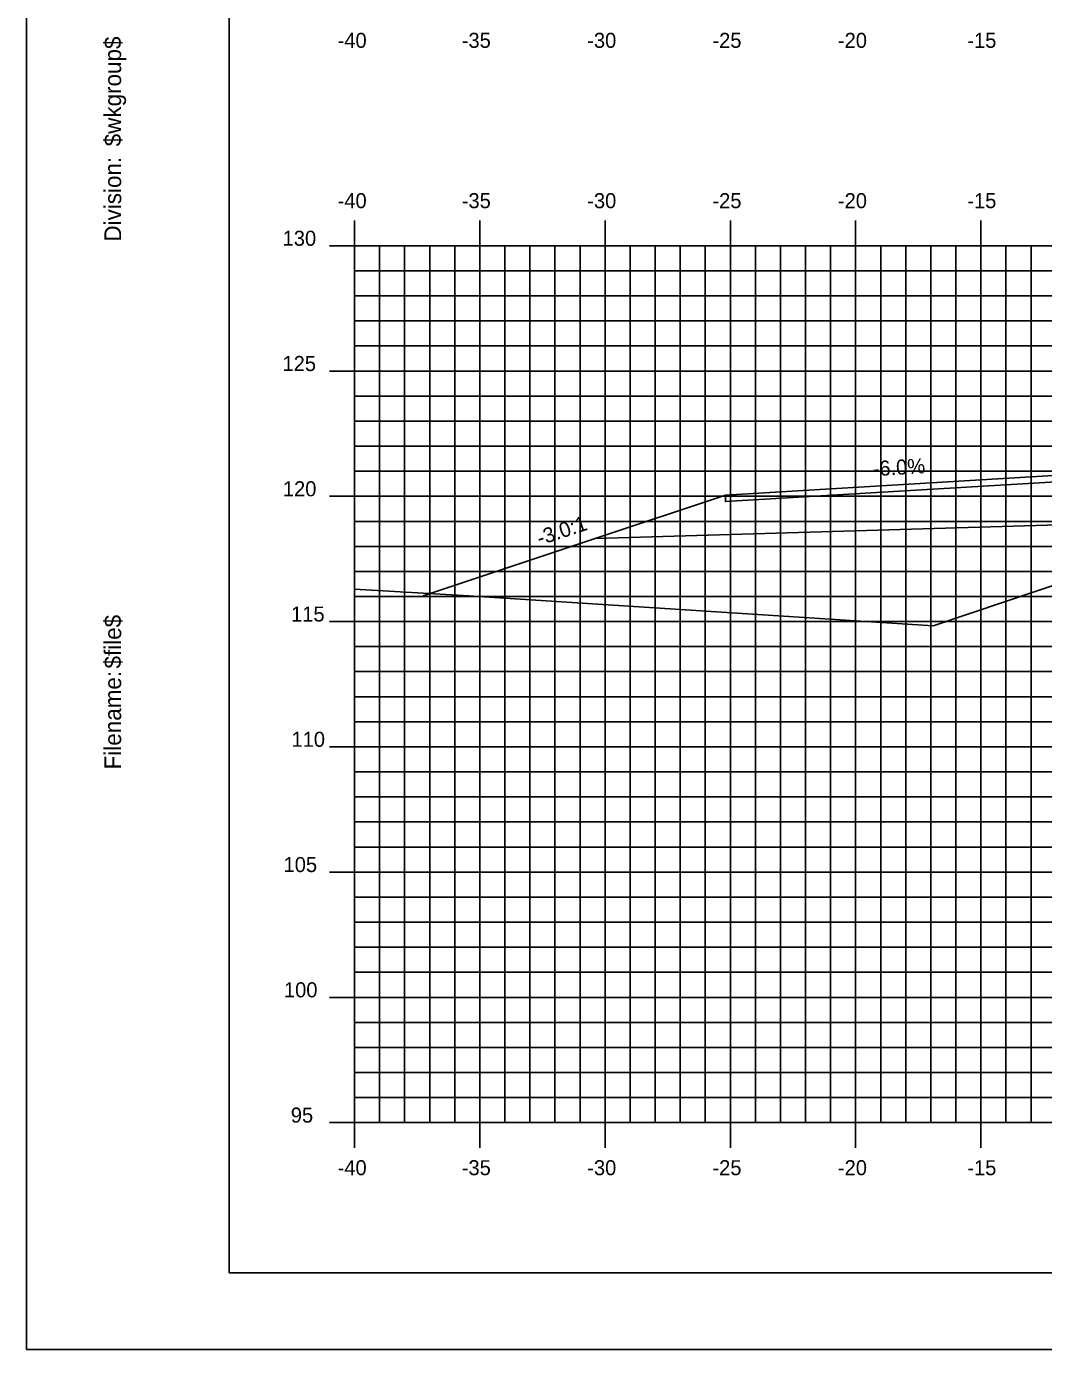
# Model space of a CAD drawing. Extents: x 850598 to 870284, y 366541 to 366651.
# Drawn here: x 859024.6 to 859065.1, y 366541.2 to 366594 of the extents above; entities that cross this region are included whole.
import ezdxf

# ---------------------------------------------------------------- set-up
doc = ezdxf.new("R2010")
doc.units = 0
for name, color, linetype in [('ANNOTATION', 7, 'Continuous'), ('BORDER', 7, 'Continuous'), ('D_Roadway_Centerline', 7, 'Continuous'), ('D_Roadway_Edge_Shoulder', 7, 'Continuous'), ('D_Roadway_SlopeLines', 7, 'Continuous'), ('D_Roadway_SubGrade', 7, 'Continuous'), ('H_V ANNOTATION', 7, 'Continuous'), ('MAJOR', 7, 'Continuous'), ('MINOR', 7, 'Continuous'), ('PLOT BOUNDARY', 7, 'Continuous'), ('S_Roadway_Centerline', 7, 'Continuous')]:
    doc.layers.add(name, color=color, linetype=linetype)

msp = doc.modelspace()

# ---------------------------------------------------------------- linework, layer by layer
at = {"layer": 'BORDER'}
for p, q in [((859032.646, 366649.225), (859032.646, 366544.225)), ((859032.646, 366544.225), (859192.646, 366544.225))]:
    msp.add_line(p, q, dxfattribs=at)
at = {"layer": 'D_Roadway_Centerline'}
msp.add_lwpolyline([(859040.387, 366571.246), (859047.257, 366573.536), (859052.446, 366575.266), (859066.646, 366576.118), (859077.646, 366576.448), (859088.646, 366576.118), (859092.646, 366575.878), (859094.646, 366575.758), (859100.646, 366573.758), (859144.638, 366563.221), (859159.828, 366559.583), (859169.69, 366557.221), (859173.69, 366557.221)], dxfattribs=at)
at = {"layer": 'D_Roadway_Edge_Shoulder'}
msp.add_lwpolyline([(859066.646, 366576.118), (859052.446, 366575.266), (859052.446, 366575.016), (859065.646, 366575.808), (859066.646, 366575.868)], close=True, dxfattribs=at)
at = {"layer": 'D_Roadway_SlopeLines'}
msp.add_lwpolyline([(859047.257, 366573.536), (859040.387, 366571.246)], dxfattribs=at)
at = {"layer": 'D_Roadway_SubGrade'}
msp.add_lwpolyline([(859066.646, 366575.618), (859065.646, 366575.558), (859065.646, 366575.808), (859052.446, 366575.016), (859052.446, 366575.266), (859047.257, 366573.536), (859066.646, 366574.118)], close=True, dxfattribs=at)
msp.add_lwpolyline([(859052.446, 366575.266), (859047.257, 366573.536), (859052.446, 366575.266)], dxfattribs=at)
at = {"layer": 'MAJOR'}
for p, q in [((859037.646, 366586.227), (859037.646, 366585.225)), ((859037.646, 366586.227), (859037.646, 366585.225)), ((859042.646, 366586.227), (859042.646, 366585.225)), ((859042.646, 366586.227), (859042.646, 366585.225)), ((859047.646, 366586.227), (859047.646, 366585.225)), ((859047.646, 366586.227), (859047.646, 366585.225)), ((859052.646, 366586.227), (859052.646, 366585.225)), ((859052.646, 366586.227), (859052.646, 366585.225)), ((859057.646, 366586.227), (859057.646, 366585.225)), ((859057.646, 366586.227), (859057.646, 366585.225)), ((859062.646, 366586.227), (859062.646, 366585.225)), ((859062.646, 366586.227), (859062.646, 366585.225)), ((859036.644, 366585.225), (859037.646, 366585.225)), ((859036.644, 366585.225), (859037.646, 366585.225)), ((859037.646, 366585.225), (859177.646, 366585.225)), ((859037.646, 366550.225), (859037.646, 366585.225)), ((859037.646, 366550.225), (859037.646, 366585.225)), ((859037.646, 366585.225), (859177.646, 366585.225)), ((859037.646, 366585.225), (859177.646, 366585.225)), ((859037.646, 366550.225), (859037.646, 366585.225)), ((859037.646, 366550.225), (859037.646, 366585.225)), ((859037.646, 366585.225), (859177.646, 366585.225)), ((859042.646, 366550.225), (859042.646, 366585.225)), ((859042.646, 366550.225), (859042.646, 366585.225)), ((859047.646, 366550.225), (859047.646, 366585.225)), ((859047.646, 366550.225), (859047.646, 366585.225)), ((859052.646, 366550.225), (859052.646, 366585.225)), ((859052.646, 366550.225), (859052.646, 366585.225)), ((859057.646, 366550.225), (859057.646, 366585.225)), ((859057.646, 366550.225), (859057.646, 366585.225)), ((859062.646, 366550.225), (859062.646, 366585.225)), ((859062.646, 366550.225), (859062.646, 366585.225)), ((859036.644, 366580.225), (859037.646, 366580.225)), ((859036.644, 366580.225), (859037.646, 366580.225)), ((859037.646, 366580.225), (859177.646, 366580.225)), ((859037.646, 366580.225), (859177.646, 366580.225)), ((859036.644, 366575.225), (859037.646, 366575.225)), ((859036.644, 366575.225), (859037.646, 366575.225)), ((859037.646, 366575.225), (859177.646, 366575.225)), ((859037.646, 366575.225), (859177.646, 366575.225)), ((859036.644, 366570.225), (859037.646, 366570.225)), ((859036.644, 366570.225), (859037.646, 366570.225)), ((859037.646, 366570.225), (859177.646, 366570.225)), ((859037.646, 366570.225), (859177.646, 366570.225)), ((859036.644, 366565.225), (859037.646, 366565.225)), ((859036.644, 366565.225), (859037.646, 366565.225)), ((859037.646, 366565.225), (859177.646, 366565.225)), ((859037.646, 366565.225), (859177.646, 366565.225)), ((859036.644, 366560.225), (859037.646, 366560.225)), ((859036.644, 366560.225), (859037.646, 366560.225)), ((859037.646, 366560.225), (859177.646, 366560.225)), ((859037.646, 366560.225), (859177.646, 366560.225)), ((859036.644, 366555.225), (859037.646, 366555.225)), ((859036.644, 366555.225), (859037.646, 366555.225)), ((859037.646, 366555.225), (859177.646, 366555.225)), ((859037.646, 366555.225), (859177.646, 366555.225)), ((859036.644, 366550.225), (859037.646, 366550.225)), ((859036.644, 366550.225), (859037.646, 366550.225)), ((859037.646, 366550.225), (859177.646, 366550.225)), ((859037.646, 366550.225), (859177.646, 366550.225)), ((859037.646, 366549.223), (859037.646, 366550.225)), ((859037.646, 366550.225), (859177.646, 366550.225)), ((859037.646, 366550.225), (859177.646, 366550.225)), ((859037.646, 366549.223), (859037.646, 366550.225)), ((859042.646, 366549.223), (859042.646, 366550.225)), ((859042.646, 366549.223), (859042.646, 366550.225)), ((859047.646, 366549.223), (859047.646, 366550.225)), ((859047.646, 366549.223), (859047.646, 366550.225)), ((859052.646, 366549.223), (859052.646, 366550.225)), ((859052.646, 366549.223), (859052.646, 366550.225)), ((859057.646, 366549.223), (859057.646, 366550.225)), ((859057.646, 366549.223), (859057.646, 366550.225)), ((859062.646, 366549.223), (859062.646, 366550.225)), ((859062.646, 366549.223), (859062.646, 366550.225))]:
    msp.add_line(p, q, dxfattribs=at)
at = {"layer": 'MINOR'}
for p, q in [((859038.646, 366550.225), (859038.646, 366585.225)), ((859038.646, 366550.225), (859038.646, 366585.225)), ((859039.646, 366550.225), (859039.646, 366585.225)), ((859039.646, 366550.225), (859039.646, 366585.225)), ((859040.646, 366550.225), (859040.646, 366585.225)), ((859040.646, 366550.225), (859040.646, 366585.225)), ((859041.646, 366550.225), (859041.646, 366585.225)), ((859041.646, 366550.225), (859041.646, 366585.225)), ((859043.646, 366550.225), (859043.646, 366585.225)), ((859043.646, 366550.225), (859043.646, 366585.225)), ((859044.646, 366550.225), (859044.646, 366585.225)), ((859044.646, 366550.225), (859044.646, 366585.225)), ((859045.646, 366550.225), (859045.646, 366585.225)), ((859045.646, 366550.225), (859045.646, 366585.225)), ((859046.646, 366550.225), (859046.646, 366585.225)), ((859046.646, 366550.225), (859046.646, 366585.225)), ((859048.646, 366550.225), (859048.646, 366585.225)), ((859048.646, 366550.225), (859048.646, 366585.225)), ((859049.646, 366550.225), (859049.646, 366585.225)), ((859049.646, 366550.225), (859049.646, 366585.225)), ((859050.646, 366550.225), (859050.646, 366585.225)), ((859050.646, 366550.225), (859050.646, 366585.225)), ((859051.646, 366550.225), (859051.646, 366585.225)), ((859051.646, 366550.225), (859051.646, 366585.225)), ((859053.646, 366550.225), (859053.646, 366585.225)), ((859053.646, 366550.225), (859053.646, 366585.225)), ((859054.646, 366550.225), (859054.646, 366585.225)), ((859054.646, 366550.225), (859054.646, 366585.225)), ((859055.646, 366550.225), (859055.646, 366585.225)), ((859055.646, 366550.225), (859055.646, 366585.225)), ((859056.646, 366550.225), (859056.646, 366585.225)), ((859056.646, 366550.225), (859056.646, 366585.225)), ((859058.646, 366550.225), (859058.646, 366585.225)), ((859058.646, 366550.225), (859058.646, 366585.225)), ((859059.646, 366550.225), (859059.646, 366585.225)), ((859059.646, 366550.225), (859059.646, 366585.225)), ((859060.646, 366550.225), (859060.646, 366585.225)), ((859060.646, 366550.225), (859060.646, 366585.225)), ((859061.646, 366550.225), (859061.646, 366585.225)), ((859061.646, 366550.225), (859061.646, 366585.225)), ((859063.646, 366550.225), (859063.646, 366585.225)), ((859063.646, 366550.225), (859063.646, 366585.225)), ((859064.646, 366550.225), (859064.646, 366585.225)), ((859064.646, 366550.225), (859064.646, 366585.225)), ((859037.646, 366584.225), (859177.646, 366584.225)), ((859037.646, 366584.225), (859038.648, 366584.225)), ((859037.646, 366584.225), (859177.646, 366584.225)), ((859037.646, 366584.225), (859038.648, 366584.225)), ((859037.646, 366583.225), (859177.646, 366583.225)), ((859037.646, 366583.225), (859038.648, 366583.225)), ((859037.646, 366583.225), (859177.646, 366583.225)), ((859037.646, 366583.225), (859038.648, 366583.225)), ((859037.646, 366582.225), (859177.646, 366582.225)), ((859037.646, 366582.225), (859038.648, 366582.225)), ((859037.646, 366582.225), (859177.646, 366582.225)), ((859037.646, 366582.225), (859038.648, 366582.225)), ((859037.646, 366581.225), (859177.646, 366581.225)), ((859037.646, 366581.225), (859038.648, 366581.225)), ((859037.646, 366581.225), (859177.646, 366581.225)), ((859037.646, 366581.225), (859038.648, 366581.225)), ((859037.646, 366579.225), (859177.646, 366579.225)), ((859037.646, 366579.225), (859038.648, 366579.225)), ((859037.646, 366579.225), (859177.646, 366579.225)), ((859037.646, 366579.225), (859038.648, 366579.225)), ((859037.646, 366578.225), (859177.646, 366578.225)), ((859037.646, 366578.225), (859038.648, 366578.225)), ((859037.646, 366578.225), (859177.646, 366578.225)), ((859037.646, 366578.225), (859038.648, 366578.225)), ((859037.646, 366577.225), (859177.646, 366577.225)), ((859037.646, 366577.225), (859038.648, 366577.225)), ((859037.646, 366577.225), (859177.646, 366577.225)), ((859037.646, 366577.225), (859038.648, 366577.225)), ((859037.646, 366576.225), (859177.646, 366576.225)), ((859037.646, 366576.225), (859038.648, 366576.225)), ((859037.646, 366576.225), (859177.646, 366576.225)), ((859037.646, 366576.225), (859038.648, 366576.225)), ((859037.646, 366574.225), (859177.646, 366574.225)), ((859037.646, 366574.225), (859038.648, 366574.225)), ((859037.646, 366574.225), (859177.646, 366574.225)), ((859037.646, 366574.225), (859038.648, 366574.225)), ((859037.646, 366573.225), (859177.646, 366573.225)), ((859037.646, 366573.225), (859038.648, 366573.225)), ((859037.646, 366573.225), (859177.646, 366573.225)), ((859037.646, 366573.225), (859038.648, 366573.225)), ((859037.646, 366572.225), (859177.646, 366572.225)), ((859037.646, 366572.225), (859038.648, 366572.225)), ((859037.646, 366572.225), (859177.646, 366572.225)), ((859037.646, 366572.225), (859038.648, 366572.225)), ((859037.646, 366571.225), (859177.646, 366571.225)), ((859037.646, 366571.225), (859038.648, 366571.225)), ((859037.646, 366571.225), (859177.646, 366571.225)), ((859037.646, 366571.225), (859038.648, 366571.225)), ((859037.646, 366569.225), (859177.646, 366569.225)), ((859037.646, 366569.225), (859038.648, 366569.225)), ((859037.646, 366569.225), (859177.646, 366569.225)), ((859037.646, 366569.225), (859038.648, 366569.225)), ((859037.646, 366568.225), (859177.646, 366568.225)), ((859037.646, 366568.225), (859038.648, 366568.225)), ((859037.646, 366568.225), (859177.646, 366568.225)), ((859037.646, 366568.225), (859038.648, 366568.225)), ((859037.646, 366567.225), (859177.646, 366567.225)), ((859037.646, 366567.225), (859038.648, 366567.225)), ((859037.646, 366567.225), (859177.646, 366567.225)), ((859037.646, 366567.225), (859038.648, 366567.225)), ((859037.646, 366566.225), (859177.646, 366566.225)), ((859037.646, 366566.225), (859038.648, 366566.225)), ((859037.646, 366566.225), (859177.646, 366566.225)), ((859037.646, 366566.225), (859038.648, 366566.225)), ((859037.646, 366564.225), (859177.646, 366564.225)), ((859037.646, 366564.225), (859038.648, 366564.225)), ((859037.646, 366564.225), (859177.646, 366564.225)), ((859037.646, 366564.225), (859038.648, 366564.225)), ((859037.646, 366563.225), (859177.646, 366563.225)), ((859037.646, 366563.225), (859038.648, 366563.225)), ((859037.646, 366563.225), (859177.646, 366563.225)), ((859037.646, 366563.225), (859038.648, 366563.225)), ((859037.646, 366562.225), (859177.646, 366562.225)), ((859037.646, 366562.225), (859038.648, 366562.225)), ((859037.646, 366562.225), (859177.646, 366562.225)), ((859037.646, 366562.225), (859038.648, 366562.225)), ((859037.646, 366561.225), (859177.646, 366561.225)), ((859037.646, 366561.225), (859038.648, 366561.225)), ((859037.646, 366561.225), (859177.646, 366561.225)), ((859037.646, 366561.225), (859038.648, 366561.225)), ((859037.646, 366559.225), (859177.646, 366559.225)), ((859037.646, 366559.225), (859038.648, 366559.225)), ((859037.646, 366559.225), (859177.646, 366559.225)), ((859037.646, 366559.225), (859038.648, 366559.225)), ((859037.646, 366558.225), (859177.646, 366558.225)), ((859037.646, 366558.225), (859038.648, 366558.225)), ((859037.646, 366558.225), (859177.646, 366558.225)), ((859037.646, 366558.225), (859038.648, 366558.225)), ((859037.646, 366557.225), (859177.646, 366557.225)), ((859037.646, 366557.225), (859038.648, 366557.225)), ((859037.646, 366557.225), (859177.646, 366557.225)), ((859037.646, 366557.225), (859038.648, 366557.225)), ((859037.646, 366556.225), (859177.646, 366556.225)), ((859037.646, 366556.225), (859038.648, 366556.225)), ((859037.646, 366556.225), (859177.646, 366556.225)), ((859037.646, 366556.225), (859038.648, 366556.225)), ((859037.646, 366554.225), (859177.646, 366554.225)), ((859037.646, 366554.225), (859038.648, 366554.225)), ((859037.646, 366554.225), (859177.646, 366554.225)), ((859037.646, 366554.225), (859038.648, 366554.225)), ((859037.646, 366553.225), (859177.646, 366553.225)), ((859037.646, 366553.225), (859038.648, 366553.225)), ((859037.646, 366553.225), (859177.646, 366553.225)), ((859037.646, 366553.225), (859038.648, 366553.225)), ((859037.646, 366552.225), (859177.646, 366552.225)), ((859037.646, 366552.225), (859038.648, 366552.225)), ((859037.646, 366552.225), (859177.646, 366552.225)), ((859037.646, 366552.225), (859038.648, 366552.225)), ((859037.646, 366551.225), (859177.646, 366551.225)), ((859037.646, 366551.225), (859038.648, 366551.225)), ((859037.646, 366551.225), (859177.646, 366551.225)), ((859037.646, 366551.225), (859038.648, 366551.225))]:
    msp.add_line(p, q, dxfattribs=at)
at = {"layer": 'PLOT BOUNDARY'}
msp.add_lwpolyline([(859024.553, 366541.166), (859194.553, 366541.166), (859194.553, 366651.166), (859024.553, 366651.166)], close=True, dxfattribs=at)
at = {"layer": 'S_Roadway_Centerline'}
msp.add_lwpolyline([(859037.646, 366571.519), (859042.207, 366571.246), (859060.734, 366570.059), (859069.32, 366572.947), (859075.992, 366575.266), (859076.994, 366575.499), (859078.054, 366575.718), (859081.313, 366575.81), (859082.104, 366575.841), (859084.255, 366575.793), (859093.309, 366575.625), (859102.537, 366575.216), (859103.849, 366575.162), (859104.343, 366575.13), (859108.051, 366574.862), (859108.956, 366574.741), (859110.463, 366574.471), (859117.98, 366573.028), (859123.451, 366571.953)], dxfattribs=at)

# ---------------------------------------------------------------- texts
at = {"layer": 'ANNOTATION'}
for s, rotation, p in [('-6.0%', 3.4336, (859058.343, 366576.021)), ('-3.0:1', 18.4348, (859045.038, 366573.25))]:
    msp.add_text(s, height=0.6, rotation=rotation, dxfattribs=at).set_placement(p)
at = {"layer": 'BORDER'}
for s, p in [('$wkgroup$', (859028.331, 366589.195)), ('Division:', (859028.331, 366585.391)), ('$file$', (859028.331, 366568.351)), ('Filename:', (859028.331, 366564.324))]:
    msp.add_text(s, height=0.6696, rotation=90, dxfattribs=at).set_placement(p)
at = {"layer": 'H_V ANNOTATION'}
for s, p in [('-40', (859036.971, 366593.125)), ('-35', (859041.926, 366593.125)), ('-30', (859046.934, 366593.125)), ('-25', (859051.931, 366593.125)), ('-20', (859056.939, 366593.125)), ('-15', (859062.103, 366593.125)), ('-40', (859036.971, 366586.725)), ('-35', (859041.926, 366586.725)), ('-30', (859046.934, 366586.725)), ('-25', (859051.931, 366586.725)), ('-20', (859056.939, 366586.725)), ('-15', (859062.103, 366586.725)), ('130', (859034.776, 366585.225)), ('125', (859034.77, 366580.225)), ('120', (859034.786, 366575.225)), ('115', (859035.113, 366570.225)), ('110', (859035.129, 366565.225)), ('105', (859034.813, 366560.225)), ('100', (859034.829, 366555.225)), ('95', (859035.102, 366550.225)), ('-40', (859036.971, 366548.125)), ('-35', (859041.926, 366548.125)), ('-30', (859046.934, 366548.125)), ('-25', (859051.931, 366548.125)), ('-20', (859056.939, 366548.125)), ('-15', (859062.103, 366548.125))]:
    msp.add_text(s, height=0.6, dxfattribs=at).set_placement(p)

doc.saveas('drawing.dxf')
